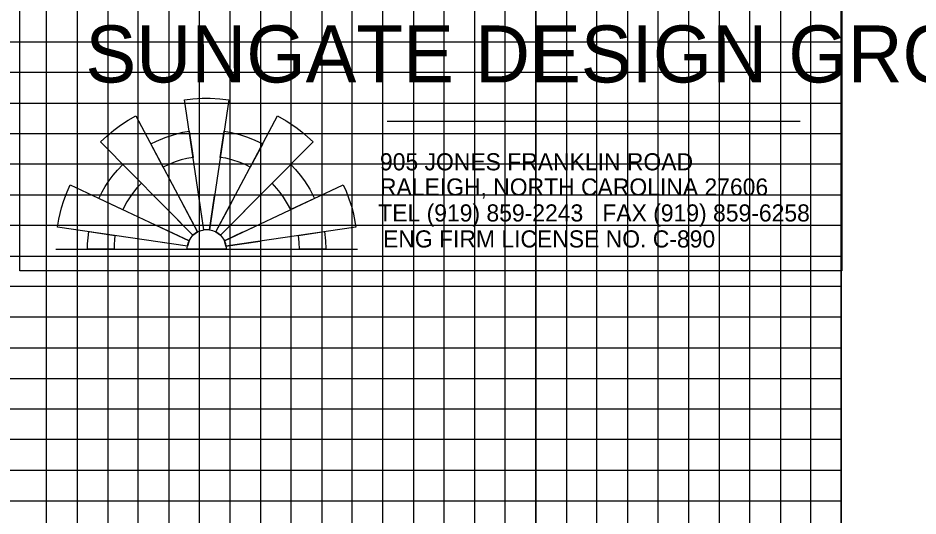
# Model space of a CAD drawing. Extents: x 2180324 to 2182216, y 74532 to 75632.
# Drawn here: x 2181656.2 to 2181803.4, y 75474.8 to 75556.2 of the extents above; entities that cross this region are included whole.
import ezdxf

# ---------------------------------------------------------------- set-up
doc = ezdxf.new("R2010")
doc.units = 0
for name, color, linetype in [('Exist Structure Minor Culvert Topo', 7, 'Continuous'), ('Exist Structure Minor Culvert Topo Terminator', 7, 'Continuous'), ('Old_Level_11', 7, 'Continuous'), ('Old_Level_2', 7, 'Continuous'), ('Sheet Cutting Line CELL', 7, 'Continuous'), ('Sheet Plot Border Outside CELL', 7, 'Continuous'), ('Sheet Sticker Exception Certification CELL', 7, 'Continuous')]:
    doc.layers.add(name, color=color, linetype=linetype)

msp = doc.modelspace()

# ---------------------------------------------------------------- linework, layer by layer
at = {"layer": 'Exist Structure Minor Culvert Topo'}
msp.add_lwpolyline([(2181300.9, 75607.28), (2181300.9, 75107.28), (2181940.9, 75107.28), (2181940.9, 75446.23), (2181790.85, 75446.23), (2181790.85, 75607.28)], close=True, dxfattribs=at)
at = {"layer": 'Exist Structure Minor Culvert Topo Terminator'}
for p, q in [((2181716.62, 75539.33), (2181784.12, 75539.33)), ((2181680.01, 75531.85), (2181680.01, 75531.85)), ((2181694.22, 75531.85), (2181694.22, 75531.85)), ((2181685.59, 75521.23), (2181682.94, 75526.22)), ((2181686.62, 75521.57), (2181685.8, 75527.15)), ((2181687.56, 75521.57), (2181688.38, 75527.15)), ((2181688.58, 75521.23), (2181691.24, 75526.22)), ((2181680.87, 75524.69), (2181684.84, 75520.68)), ((2181693.31, 75524.69), (2181689.33, 75520.68)), ((2181684.21, 75519.77), (2181679.09, 75522.17)), ((2181680.49, 75521.53), (2181680.49, 75521.53)), ((2181689.97, 75519.77), (2181695.08, 75522.17)), ((2181669.83, 75520.96), (2181669.83, 75520.96)), ((2181692.93, 75521.16), (2181689.97, 75519.77)), ((2181683.94, 75518.88), (2181678.35, 75519.72)), ((2181690.24, 75518.88), (2181695.83, 75519.72)), ((2181662.41, 75518.42), (2181711.76, 75518.42))]:
    msp.add_line(p, q, dxfattribs=at)
for points in [[(2181656.55, 75558.85), (2181790.95, 75558.85), (2181790.95, 75514.84), (2181656.55, 75514.84)], [(2181686.62, 75521.57), (2181683.48, 75542.83), (2181684.84, 75542.99), (2181686.37, 75543.08), (2181687.67, 75543.09), (2181689.25, 75543), (2181690.7, 75542.83), (2181687.56, 75521.57)], [(2181684.84, 75520.68), (2181669.71, 75535.94), (2181670.73, 75536.89), (2181671.88, 75537.84), (2181673.01, 75538.68), (2181674.27, 75539.5), (2181675.5, 75540.2), (2181685.59, 75521.23)], [(2181688.58, 75521.23), (2181698.67, 75540.2), (2181700.09, 75539.39), (2181701.66, 75538.33), (2181702.65, 75537.57), (2181703.57, 75536.78), (2181704.47, 75535.94), (2181689.33, 75520.68)], [(2181677.94, 75535.63), (2181678.87, 75536.09), (2181680.28, 75536.68), (2181681.8, 75537.18), (2181683.17, 75537.51), (2181684.23, 75537.7), (2181684.87, 75533.42), (2181683.86, 75533.24), (2181682.91, 75533), (2181681.93, 75532.68), (2181680.9, 75532.27), (2181679.97, 75531.81)], [(2181689.94, 75537.7), (2181691.12, 75537.49), (2181692.44, 75537.16), (2181693.77, 75536.73), (2181694.97, 75536.24), (2181696.24, 75535.63), (2181694.21, 75531.81), (2181693.49, 75532.17), (2181692.54, 75532.57), (2181691.18, 75533.03), (2181690.22, 75533.26), (2181689.31, 75533.42)], [(2181669.44, 75526.69), (2181669.99, 75527.78), (2181670.49, 75528.64), (2181671.14, 75529.62), (2181671.78, 75530.48), (2181672.49, 75531.34), (2181673.36, 75532.26), (2181676.41, 75529.19), (2181675.68, 75528.41), (2181675.1, 75527.72), (2181674.56, 75526.98), (2181674.03, 75526.13), (2181673.65, 75525.45), (2181673.35, 75524.85)], [(2181700.82, 75532.26), (2181701.6, 75531.43), (2181702.37, 75530.52), (2181703.08, 75529.57), (2181703.96, 75528.19), (2181704.73, 75526.71), (2181700.82, 75524.87), (2181700.32, 75525.84), (2181699.65, 75526.92), (2181699.1, 75527.68), (2181698.57, 75528.34), (2181697.77, 75529.19)], [(2181683.94, 75518.88), (2181662.68, 75522.02), (2181662.91, 75523.31), (2181663.36, 75525.19), (2181663.72, 75526.34), (2181664.27, 75527.8), (2181664.75, 75528.9), (2181684.21, 75519.77)], [(2181689.97, 75519.75), (2181709.42, 75528.92), (2181709.88, 75527.88), (2181710.35, 75526.65), (2181710.8, 75525.25), (2181711.1, 75524.13), (2181711.5, 75522.03), (2181690.24, 75518.88)], [(2181683.9, 75518.42), (2181683.91, 75518.66), (2181683.94, 75518.88), (2181684.05, 75519.38), (2181684.21, 75519.77), (2181684.36, 75520.06), (2181684.54, 75520.32), (2181684.7, 75520.53), (2181684.84, 75520.68), (2181685.21, 75520.99), (2181685.59, 75521.23), (2181685.86, 75521.36), (2181686.16, 75521.47), (2181686.43, 75521.53), (2181686.62, 75521.57), (2181687.1, 75521.6), (2181687.56, 75521.57), (2181687.83, 75521.52), (2181688.06, 75521.45), (2181688.31, 75521.36), (2181688.58, 75521.23), (2181688.98, 75520.98), (2181689.33, 75520.68), (2181689.51, 75520.49), (2181689.69, 75520.26), (2181689.82, 75520.06), (2181689.97, 75519.77), (2181690.15, 75519.31), (2181690.24, 75518.88), (2181690.27, 75518.64), (2181690.28, 75518.42)], [(2181667.6, 75518.42), (2181667.62, 75519.26), (2181667.68, 75520.25), (2181667.81, 75521.27), (2181672.08, 75520.63), (2181671.99, 75519.91), (2181671.94, 75519.17), (2181671.93, 75518.42)], [(2181706.37, 75521.27), (2181706.53, 75519.79), (2181706.58, 75518.45), (2181702.26, 75518.42), (2181702.22, 75519.52), (2181702.1, 75520.64)]]:
    msp.add_lwpolyline(points, close=True, dxfattribs=at)
for start, end in [(0, 180), (180, 0)]:
    msp.add_arc((2181747.39, 75524.44), 0.138, start, end, dxfattribs=at)
at = {"layer": 'Old_Level_11'}
for p, q in [((2181690.9, 75107.28), (2181690.9, 75607.28)), ((2181740.9, 75107.28), (2181740.9, 75607.28)), ((2181790.85, 75507.28), (2180490.9, 75507.28))]:
    msp.add_line(p, q, dxfattribs=at)
at = {"layer": 'Old_Level_2'}
for points in [[(2181265.9, 75107.28), (2181315.9, 75107.28), (2181315.9, 75607.28), (2181365.9, 75607.28), (2181365.9, 75107.28), (2181415.9, 75107.28), (2181415.9, 75607.28), (2181465.9, 75607.28), (2181465.9, 75107.28), (2181515.9, 75107.28), (2181515.9, 75607.28), (2181565.9, 75607.28), (2181565.9, 75107.28), (2181615.9, 75107.28), (2181615.9, 75607.28), (2181665.9, 75607.28), (2181665.9, 75107.28), (2181715.9, 75107.28), (2181715.9, 75607.28), (2181765.9, 75607.28), (2181765.9, 75107.28), (2181815.9, 75107.28), (2181815.9, 75446.23)], [(2181790.9, 75532.28), (2180490.9, 75532.28), (2180490.9, 75482.28), (2181790.9, 75482.28)]]:
    msp.add_lwpolyline(points, dxfattribs=at)
at = {"layer": 'Sheet Cutting Line CELL'}
msp.add_lwpolyline([(2181790.85, 75582.23), (2181890.9, 75582.23), (2181890.9, 75469.73), (2181790.85, 75469.73)], close=True, dxfattribs=at)
at = {"layer": 'Sheet Plot Border Outside CELL'}
for points in [[(2181660.9, 75107.28), (2181660.9, 75607.28), (2181670.9, 75607.28), (2181670.9, 75107.28)], [(2181675.9, 75107.28), (2181675.9, 75607.28), (2181680.9, 75607.28), (2181680.9, 75107.28)], [(2181685.9, 75107.28), (2181685.9, 75607.28), (2181695.9, 75607.28), (2181695.9, 75107.28)], [(2181700.9, 75107.28), (2181700.9, 75607.28), (2181705.9, 75607.28), (2181705.9, 75107.28)], [(2181710.9, 75107.28), (2181710.9, 75607.28), (2181720.9, 75607.28), (2181720.9, 75107.28)], [(2181725.9, 75107.28), (2181725.9, 75607.28), (2181730.9, 75607.28), (2181730.9, 75107.28)], [(2181735.9, 75107.28), (2181735.9, 75607.28), (2181745.9, 75607.28), (2181745.9, 75107.28)], [(2181750.9, 75107.28), (2181750.9, 75607.28), (2181755.9, 75607.28), (2181755.9, 75107.28)], [(2181760.9, 75107.28), (2181760.9, 75607.28), (2181770.9, 75607.28), (2181770.9, 75107.28)], [(2181775.9, 75107.28), (2181775.9, 75607.28), (2181780.9, 75607.28), (2181780.9, 75107.28)], [(2181785.9, 75107.28), (2181785.9, 75607.28), (2181795.9, 75607.28)], [(2181790.9, 75562.28), (2180540.9, 75562.28), (2180540.9, 75552.28), (2181790.9, 75552.28)], [(2181790.9, 75547.28), (2180540.9, 75547.28), (2180540.9, 75542.28), (2181790.9, 75542.28)], [(2181790.9, 75537.28), (2180540.9, 75537.28), (2180540.9, 75527.28), (2181790.9, 75527.28)], [(2181790.9, 75522.28), (2180540.9, 75522.28), (2180540.9, 75517.28), (2181790.9, 75517.28)], [(2181790.9, 75512.28), (2180540.9, 75512.28), (2180540.9, 75502.28), (2181790.9, 75502.28)], [(2181790.9, 75497.18), (2180541, 75497.18), (2180541, 75492.28), (2181790.9, 75492.28)], [(2181790.9, 75487.28), (2180540.9, 75487.28), (2180540.9, 75477.28), (2181790.9, 75477.28)]]:
    msp.add_lwpolyline(points, dxfattribs=at)
at = {"layer": 'Sheet Sticker Exception Certification CELL'}
for points in [[(2181240.9, 75107.28), (2181290.9, 75107.28), (2181290.9, 75607.28), (2181340.9, 75607.28), (2181340.9, 75107.28), (2181390.9, 75107.28), (2181390.9, 75607.28), (2181440.9, 75607.28), (2181440.9, 75107.28), (2181490.9, 75107.28), (2181490.9, 75607.28), (2181540.9, 75607.28), (2181540.9, 75107.28), (2181590.9, 75107.28), (2181590.9, 75607.28), (2181640.9, 75607.28), (2181640.9, 75107.28), (2181690.9, 75107.28), (2181690.9, 75607.28), (2181740.9, 75607.28), (2181740.9, 75107.28), (2181790.9, 75107.28), (2181790.9, 75607.28), (2181817.2, 75607.28)], [(2181790.9, 75507.28), (2180490.9, 75507.28), (2180490.9, 75457.28), (2181790.9, 75457.28)]]:
    msp.add_lwpolyline(points, dxfattribs=at)

# ---------------------------------------------------------------- texts
at = {"layer": 'Exist Structure Minor Culvert Topo Terminator'}
for s, height, p in [('SUNGATE DESIGN GROUP, P.A.', 9.3194, (2181667.25, 75545.66)), ('905 JONES FRANKLIN ROAD', 2.8007, (2181715.42, 75531.29)), ('RALEIGH, NORTH CAROLINA 27606', 2.8007, (2181715.42, 75527.17)), ('TEL (919) 859-2243   FAX (919) 859-6258', 2.8007, (2181715.14, 75522.93)), ('ENG FIRM LICENSE NO. C-890', 2.8007, (2181715.92, 75518.68))]:
    msp.add_text(s, height=height, dxfattribs=at).set_placement(p)

doc.saveas('drawing.dxf')
